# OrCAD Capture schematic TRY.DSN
size A3
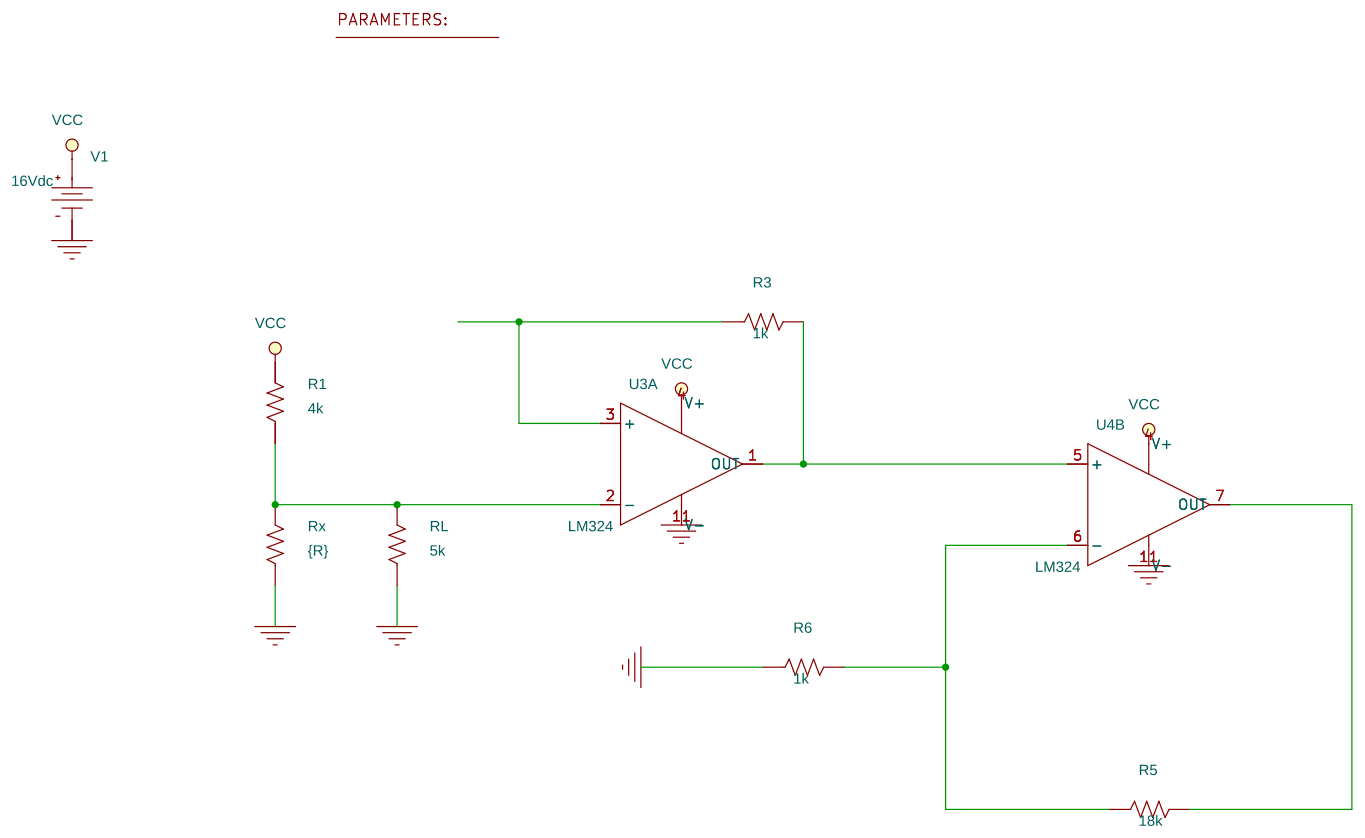
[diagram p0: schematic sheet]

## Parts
1  PARAM
R1  4k  [AX/RC05]
R3  1k  [AX/RC05]
R5  18k  [AX/RC05]
R6  1k  [AX/RC05]
RL  5k  [AX/RC05]
Rx  {R}  [AX/RC05]
U3  LM324  [DIP.100/14/W.300/L.800]  (section A)
U4  LM324  [DIP.100/14/W.300/L.800]  (section B)
V1  VDC

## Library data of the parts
1 = PARAM: R: 20k
R1 R3 R5 R6 RL Rx = R
U3 U4 = LM324
V1 = VDC: DC: 16Vdc

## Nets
VCC: R1.2 U3.4(V+) U4.4(V+) V1.0(+)
0: R6.1 RL.1 Rx.1 U3.11(V-) U4.11(V-) V1.1(-)
N05603: R1.1 RL.2 Rx.2 U3.2(-)
N10287: R3.1 U3.3(+)
N10319: R3.2 U3.1(OUT) U4.5(+)
N10331: R5.1 R6.2 U4.6(-)
N10339: R5.2 U4.7(OUT)
